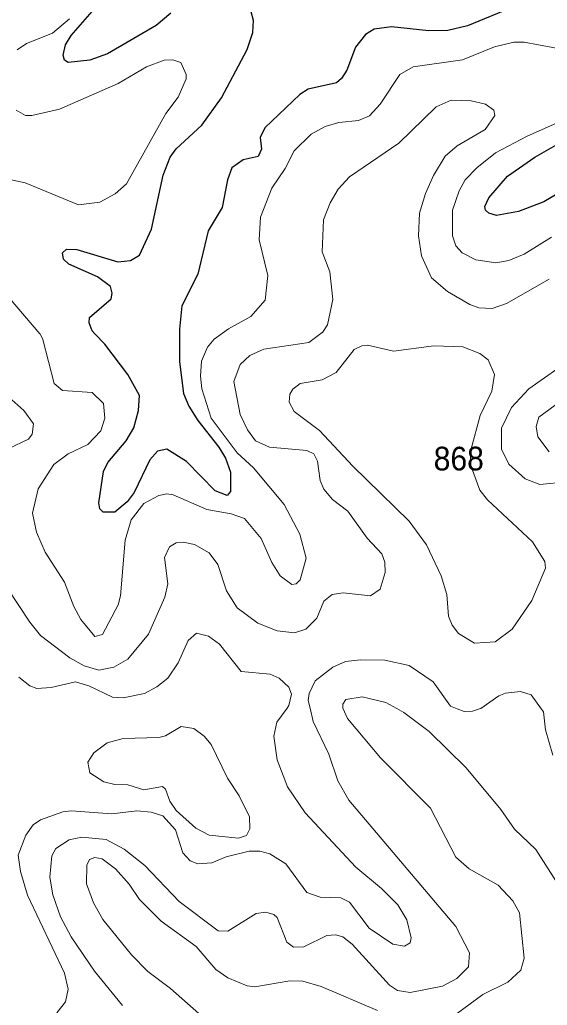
# Model space of a CAD drawing. Extents: x 473.9 to 500, y 7733.1 to 7760.8.
# Drawn here: x 492.567 to 494.35, y 7740.071 to 7743.401 of the extents above; entities that cross this region are included whole.
import ezdxf

# ---------------------------------------------------------------- set-up
doc = ezdxf.new("R2010")
doc.units = 0
doc.header["$LTSCALE"] = 0.032
doc.layers.add('1', color=7, linetype='Continuous', lineweight=25)
doc.layers.add('2', color=7, linetype='Continuous', lineweight=13)
doc.layers.add('21', color=7, linetype='Continuous')

msp = doc.modelspace()

# ---------------------------------------------------------------- linework, layer by layer
at = {"layer": '1'}
for points in [[(494.2391, 7743.4457), (494.0809, 7743.3806), (494.0139, 7743.3648), (493.9495, 7743.364), (493.8232, 7743.3775), (493.765, 7743.3698), (493.7356, 7743.351), (493.7022, 7743.3087), (493.6728, 7743.2313), (493.6549, 7743.203), (493.6374, 7743.1877), (493.5423, 7743.1662), (493.5135, 7743.1492), (493.3958, 7743.0359), (493.3804, 7743.0035), (493.3846, 7742.9634), (493.3732, 7742.939), (493.3221, 7742.9282), (493.2841, 7742.9011), (493.269, 7742.8602), (493.2515, 7742.7666), (493.2043, 7742.688), (493.1693, 7742.5417), (493.1152, 7742.4347), (493.1077, 7742.3552), (493.1076, 7742.3416), (493.1068, 7742.2449), (493.1211, 7742.1383), (493.1387, 7742.0949), (493.1687, 7742.0469), (493.2402, 7741.9568), (493.2625, 7741.9195), (493.2797, 7741.8718), (493.2795, 7741.8067), (493.2687, 7741.7938), (493.2278, 7741.8093), (493.1314, 7741.9079), (493.0639, 7741.95), (493.0325, 7741.9433), (493.0067, 7741.9139), (492.9535, 7741.8039), (492.9299, 7741.7719), (492.8882, 7741.7366), (492.8491, 7741.7369), (492.8379, 7741.7484), (492.8343, 7741.7683), (492.8502, 7741.8745), (492.8648, 7741.9046), (492.9275, 7741.978), (492.9531, 7742.0217), (492.9692, 7742.0809), (492.9725, 7742.1309), (492.9323, 7742.2021), (492.8551, 7742.3044), (492.8216, 7742.3403), (492.8125, 7742.35), (492.8024, 7742.3768), (492.8034, 7742.3954), (492.8761, 7742.4578), (492.8799, 7742.4767), (492.8741, 7742.4995), (492.8306, 7742.5327), (492.7329, 7742.5756), (492.7154, 7742.5923), (492.7115, 7742.6139), (492.7255, 7742.6265), (492.7599, 7742.6245), (492.8992, 7742.5832), (492.9411, 7742.5875), (492.9726, 7742.6059), (493.0127, 7742.6941), (493.0515, 7742.8764), (493.0752, 7742.9364), (493.096, 7742.9654), (493.1831, 7743.0446), (493.2496, 7743.1374), (493.3358, 7743.3006), (493.3549, 7743.3586), (493.3577, 7743.3988), (493.3417, 7743.4574)], [(492.7185, 7743.2647), (492.7139, 7743.2812), (492.7225, 7743.3169), (492.7413, 7743.3475), (492.8279, 7743.4467)], [(493.0782, 7743.4238), (493.0281, 7743.3816), (492.8642, 7743.2857), (492.8047, 7743.2648), (492.7309, 7743.2572), (492.7185, 7743.2647)], [(494.4843, 7742.8718), (494.3388, 7742.7864), (494.2531, 7742.753), (494.1782, 7742.7402), (494.1525, 7742.7479), (494.1413, 7742.7573), (494.1393, 7742.7698), (494.1522, 7742.7996), (494.2155, 7742.8726), (494.3083, 7742.9374), (494.4501, 7743.0182)]]:
    msp.add_lwpolyline(points, dxfattribs=at)
at = {"layer": '2'}
for points in [[(492.7355, 7743.4044), (492.6777, 7743.3564), (492.5899, 7743.3212), (492.5582, 7743.2999)], [(492.7308, 7741.9342), (492.6831, 7741.8982), (492.6299, 7741.8155), (492.6108, 7741.7337), (492.6242, 7741.6699), (492.6534, 7741.6023), (492.7191, 7741.501), (492.7496, 7741.4179), (492.7737, 7741.374), (492.8214, 7741.3172), (492.8465, 7741.3242), (492.8995, 7741.4239), (492.9082, 7741.4549), (492.9233, 7741.6429), (492.9434, 7741.711), (492.9872, 7741.7664), (493.037, 7741.7934), (493.0647, 7741.7991), (493.0863, 7741.7957), (493.1993, 7741.7458), (493.2817, 7741.732), (493.3274, 7741.7158), (493.3834, 7741.6485), (493.4188, 7741.5669), (493.4476, 7741.5223), (493.4864, 7741.493), (493.5011, 7741.4952), (493.5153, 7741.5079), (493.5354, 7741.5816), (493.5141, 7741.6624), (493.4613, 7741.7631), (493.3576, 7741.8869), (493.3022, 7741.9382), (493.2145, 7742.055), (493.1828, 7742.1541), (493.1777, 7742.1967), (493.1816, 7742.2471), (493.2016, 7742.2945), (493.2242, 7742.3218), (493.2527, 7742.3422), (493.2725, 7742.3564), (493.3484, 7742.3979), (493.3968, 7742.4541), (493.4059, 7742.5365), (493.3762, 7742.6577), (493.3806, 7742.7341), (493.4193, 7742.8319), (493.4638, 7742.899), (493.4943, 7742.9586), (493.5524, 7743.0149), (493.5998, 7743.0409), (493.6457, 7743.0542), (493.7117, 7743.0603), (493.7492, 7743.0769), (493.7858, 7743.1157), (493.8514, 7743.2167), (493.8973, 7743.2422), (494.0636, 7743.2654), (494.1723, 7743.3098), (494.2375, 7743.3251), (494.2718, 7743.3253), (494.5144, 7743.28)], [(492.5552, 7743.0955), (492.5869, 7743.0781), (492.6085, 7743.0777), (492.7016, 7743.0994), (492.8996, 7743.186), (492.9956, 7743.2427), (493.055, 7743.2648), (493.0846, 7743.2658), (493.1123, 7743.2564), (493.1301, 7743.2162), (493.1297, 7743.2014), (493.1029, 7743.1401), (493.061, 7743.0841), (492.9287, 7742.847), (492.8902, 7742.8124), (492.8384, 7742.7849), (492.7663, 7742.776), (492.5855, 7742.8497), (492.5285, 7742.8625)], [(492.601, 7741.365), (492.6378, 7741.3202), (492.7364, 7741.2454), (492.7855, 7741.2175), (492.8348, 7741.2036), (492.8857, 7741.2133), (492.9323, 7741.2405), (493.0021, 7741.3252), (493.0577, 7741.4496), (493.0675, 7741.4948), (493.0564, 7741.5839), (493.0735, 7741.6195), (493.0958, 7741.6336), (493.1199, 7741.636), (493.1579, 7741.6275), (493.2078, 7741.5994), (493.2364, 7741.56), (493.2657, 7741.4714), (493.3023, 7741.4134), (493.3724, 7741.3623), (493.4378, 7741.3361), (493.4962, 7741.3298), (493.5341, 7741.3416), (493.5715, 7741.3789), (493.5949, 7741.4366), (493.6236, 7741.4585), (493.6607, 7741.464), (493.753, 7741.4545), (493.7857, 7741.4765), (493.8022, 7741.5337), (493.8014, 7741.568), (493.7915, 7741.5963), (493.7419, 7741.6493), (493.6756, 7741.741), (493.6247, 7741.78), (493.5949, 7741.8145), (493.5824, 7741.8436), (493.5739, 7741.9094), (493.5615, 7741.9341), (493.5374, 7741.9459), (493.4114, 7741.9564), (493.3644, 7741.9782), (493.3369, 7742.0159), (493.3125, 7742.0675), (493.2911, 7742.1785), (493.312, 7742.2358), (493.3451, 7742.267), (493.3922, 7742.2881), (493.544, 7742.3103), (493.589, 7742.3438), (493.59, 7742.3445), (493.6079, 7742.3699), (493.6253, 7742.4556), (493.6157, 7742.5492), (493.5896, 7742.6165), (493.5941, 7742.7247), (493.6163, 7742.7821), (493.6438, 7742.8292), (493.6815, 7742.8702), (493.8482, 7742.9839), (493.9748, 7743.107), (494.0259, 7743.129), (494.0933, 7743.1275), (494.141, 7743.1156), (494.1691, 7743.0952), (494.1728, 7743.0777), (494.1403, 7743.0302), (494.0458, 7742.9754), (494.005, 7742.9401), (493.9652, 7742.8754), (493.9383, 7742.8146), (493.9187, 7742.7477), (493.9149, 7742.6705), (493.9254, 7742.6036), (493.9587, 7742.529), (494.0132, 7742.4829), (494.088, 7742.4387), (494.1192, 7742.4277), (494.1641, 7742.4249), (494.2125, 7742.4422), (494.3565, 7742.5249)], [(494.5034, 7743.1058), (494.2825, 7743.0082), (494.1751, 7742.9511), (494.1117, 7742.9004), (494.0725, 7742.8597), (494.0527, 7742.8233), (494.0301, 7742.7574), (494.0297, 7742.6713), (494.0414, 7742.6374), (494.0622, 7742.6133), (494.1084, 7742.5895), (494.1763, 7742.58), (494.2197, 7742.5871), (494.2718, 7742.609), (494.3649, 7742.6668)], [(492.5059, 7742.4916), (492.6358, 7742.3394), (492.6359, 7742.3393), (492.6459, 7742.3206), (492.6836, 7742.1716), (492.7116, 7742.1484), (492.8118, 7742.1411), (492.8504, 7742.1039), (492.8551, 7742.0547), (492.8412, 7742.0124), (492.798, 7741.9661), (492.7308, 7741.9342)], [(494.4359, 7742.2575), (494.2877, 7742.1539), (494.2291, 7742.0913), (494.1949, 7742.0214), (494.195, 7741.9501), (494.2207, 7741.8994), (494.2756, 7741.8496), (494.3255, 7741.8307), (494.416, 7741.8391)], [(492.5103, 7742.144), (492.5809, 7742.0806), (492.6139, 7742.0356), (492.6096, 7742.0011), (492.5971, 7741.9835), (492.5303, 7741.9521)], [(494.3935, 7742.1116), (494.3217, 7742.0583), (494.3121, 7742.0264), (494.3188, 7741.9922), (494.3564, 7741.9407)], [(492.5245, 7741.4815), (492.601, 7741.365)], [(492.6923, 7740.0446), (492.7222, 7740.0822), (492.7311, 7740.1256), (492.7186, 7740.1787), (492.5935, 7740.4424), (492.5703, 7740.5228), (492.5617, 7740.5775), (492.5881, 7740.645), (492.6127, 7740.6805), (492.6378, 7740.6972), (492.7125, 7740.7249), (492.7415, 7740.7283), (492.8788, 7740.7171), (492.963, 7740.7282), (493.0111, 7740.7235), (493.0512, 7740.7114), (493.0938, 7740.6636), (493.1187, 7740.5863), (493.1435, 7740.5589), (493.1688, 7740.5483), (493.2161, 7740.5523), (493.2646, 7740.5728), (493.3429, 7740.5909), (493.3793, 7740.5916), (493.4126, 7740.5822), (493.467, 7740.549), (493.5375, 7740.4513), (493.583, 7740.4363), (493.6527, 7740.4332), (493.6823, 7740.4187), (493.7479, 7740.3307), (493.8282, 7740.2774), (493.8671, 7740.2701), (493.8873, 7740.2821), (493.89, 7740.2984), (493.8752, 7740.3599), (493.8452, 7740.4102), (493.79, 7740.4655), (493.7037, 7740.5374), (493.5314, 7740.7211), (493.4726, 7740.8094), (493.4376, 7740.9001), (493.4261, 7740.9796), (493.4367, 7741.0272), (493.4708, 7741.0751), (493.4772, 7741.084), (493.4854, 7741.122), (493.4771, 7741.1457), (493.4439, 7741.1757), (493.4142, 7741.1899), (493.3161, 7741.1991), (493.2429, 7741.2915), (493.2057, 7741.3176), (493.1652, 7741.3281), (493.1366, 7741.3039), (493.1028, 7741.2276), (493.0674, 7741.1762), (493.031, 7741.1466), (492.9892, 7741.1244), (492.9167, 7741.1093), (492.8804, 7741.1117), (492.8008, 7741.1501), (492.756, 7741.1632), (492.674, 7741.145), (492.6253, 7741.1411), (492.602, 7741.1507), (492.5645, 7741.179)], [(494.3687, 7740.9157), (494.3441, 7741.0015), (494.3378, 7741.0619), (494.3312, 7741.0711), (494.2962, 7741.1199), (494.2595, 7741.1311), (494.2091, 7741.1259), (494.1862, 7741.1163), (494.1258, 7741.0738), (494.1208, 7741.0721), (494.098, 7741.0641), (494.0697, 7741.063), (494.046, 7741.0724), (494.0234, 7741.0814), (493.9646, 7741.1633), (493.8833, 7741.2191), (493.8017, 7741.2364), (493.7184, 7741.2381), (493.6683, 7741.2319), (493.6259, 7741.2134), (493.5657, 7741.1669), (493.545, 7741.1247), (493.5426, 7741.1003), (493.5485, 7741.0747), (493.5588, 7741.0299), (493.6119, 7740.9198), (493.6419, 7740.8294), (493.6797, 7740.7641), (494.0407, 7740.3372), (494.0876, 7740.2483), (494.0838, 7740.2006), (494.0447, 7740.1612), (493.9957, 7740.1353), (493.8865, 7740.1142), (493.8441, 7740.1209), (493.8164, 7740.1387), (493.6913, 7740.2773), (493.6597, 7740.3019), (493.635, 7740.3086), (493.6056, 7740.306), (493.5272, 7740.2678), (493.492, 7740.2672), (493.4698, 7740.2843), (493.4368, 7740.3674), (493.4258, 7740.3774), (493.3992, 7740.3857), (493.3658, 7740.3803), (493.2706, 7740.3206), (493.2374, 7740.3221), (493.1065, 7740.4216), (492.9901, 7740.5432), (492.9197, 7740.5984), (492.8595, 7740.6305), (492.7776, 7740.6391), (492.734, 7740.6297), (492.6896, 7740.6005), (492.6753, 7740.5752), (492.6694, 7740.5035), (492.6797, 7740.4435), (492.7054, 7740.3696), (492.7412, 7740.302), (492.8195, 7740.1861), (492.9146, 7740.0698)], [(494.3795, 7740.4912), (494.312, 7740.5973), (494.2389, 7740.6657), (494.1927, 7740.7328), (494.0765, 7740.8736), (493.9505, 7740.9956), (493.865, 7741.0604), (493.8415, 7741.0734), (493.804, 7741.094), (493.7246, 7741.1134), (493.6692, 7741.1038), (493.6594, 7741.0888), (493.6592, 7741.0754), (493.6597, 7741.0742), (493.6746, 7741.0393), (493.7871, 7740.9068), (493.955, 7740.7373), (494.0411, 7740.5707), (494.0863, 7740.5315), (494.1845, 7740.4762), (494.2339, 7740.4231), (494.2562, 7740.383), (494.2719, 7740.2296), (494.2613, 7740.1888), (494.2163, 7740.1482), (494.1324, 7740.1071), (494.042, 7740.0409)], [(493.776, 7740.0526), (493.586, 7740.1341), (493.5241, 7740.1525), (493.4796, 7740.1527), (493.3622, 7740.1334), (493.3364, 7740.1366), (493.2706, 7740.1629), (493.2305, 7740.1921), (493.1633, 7740.2696), (493.0457, 7740.3552), (492.9718, 7740.4277), (492.9368, 7740.4804), (492.8905, 7740.5313), (492.846, 7740.5656), (492.8208, 7740.5705), (492.8033, 7740.5628), (492.7943, 7740.5442), (492.7931, 7740.481), (492.8161, 7740.4166), (492.8477, 7740.3607), (492.9453, 7740.2407), (492.9997, 7740.1849), (493.0763, 7740.1278), (493.2105, 7740.0095)]]:
    msp.add_lwpolyline(points, dxfattribs=at)
for points in [[(493.8835, 7741.7065), (493.693, 7741.8927), (493.5807, 7742.0134), (493.4948, 7742.077), (493.4783, 7742.1088), (493.4802, 7742.1363), (493.4898, 7742.1531), (493.515, 7742.1717), (493.5899, 7742.1848), (493.6368, 7742.2095), (493.6981, 7742.2866), (493.723, 7742.2991), (493.7426, 7742.301), (493.8307, 7742.2817), (493.9669, 7742.2993), (494.065, 7742.2959), (494.1222, 7742.2728), (494.1509, 7742.252), (494.1721, 7742.2027), (494.1632, 7742.1459), (494.1231, 7742.0638), (494.0933, 7741.9507), (494.0893, 7741.9), (494.1224, 7741.8114), (494.148, 7741.7785), (494.3007, 7741.6366), (494.3415, 7741.5707), (494.344, 7741.5476), (494.2978, 7741.4388), (494.232, 7741.3414), (494.1743, 7741.2988), (494.104, 7741.2948), (494.0505, 7741.3273), (494.0285, 7741.3556), (494.0164, 7741.3858), (494.0106, 7741.4587), (493.9919, 7741.522), (493.9421, 7741.6264)], [(493.3442, 7740.7075), (493.3089, 7740.7785), (493.2695, 7740.8378), (493.2142, 7740.9515), (493.1909, 7740.9796), (493.1555, 7741.0061), (493.1125, 7741.0129), (493.0604, 7740.9817), (493.0369, 7740.9755), (492.9168, 7740.9717), (492.863, 7740.9581), (492.8178, 7740.9234), (492.7975, 7740.892), (492.8041, 7740.8567), (492.8514, 7740.826), (492.8889, 7740.8168), (492.9323, 7740.8151), (492.9865, 7740.7984), (493.0493, 7740.8105), (493.0603, 7740.8008), (493.075, 7740.7609), (493.0963, 7740.7285), (493.1626, 7740.6692), (493.2074, 7740.6457), (493.3065, 7740.6355), (493.3338, 7740.6441), (493.3455, 7740.6664)]]:
    msp.add_lwpolyline(points, close=True, dxfattribs=at)

# ---------------------------------------------------------------- texts
at = {"layer": '21', "width": 0.95}
msp.add_text('868', height=0.08, dxfattribs=at).set_placement((493.9663, 7741.8782))

doc.saveas('drawing.dxf')
